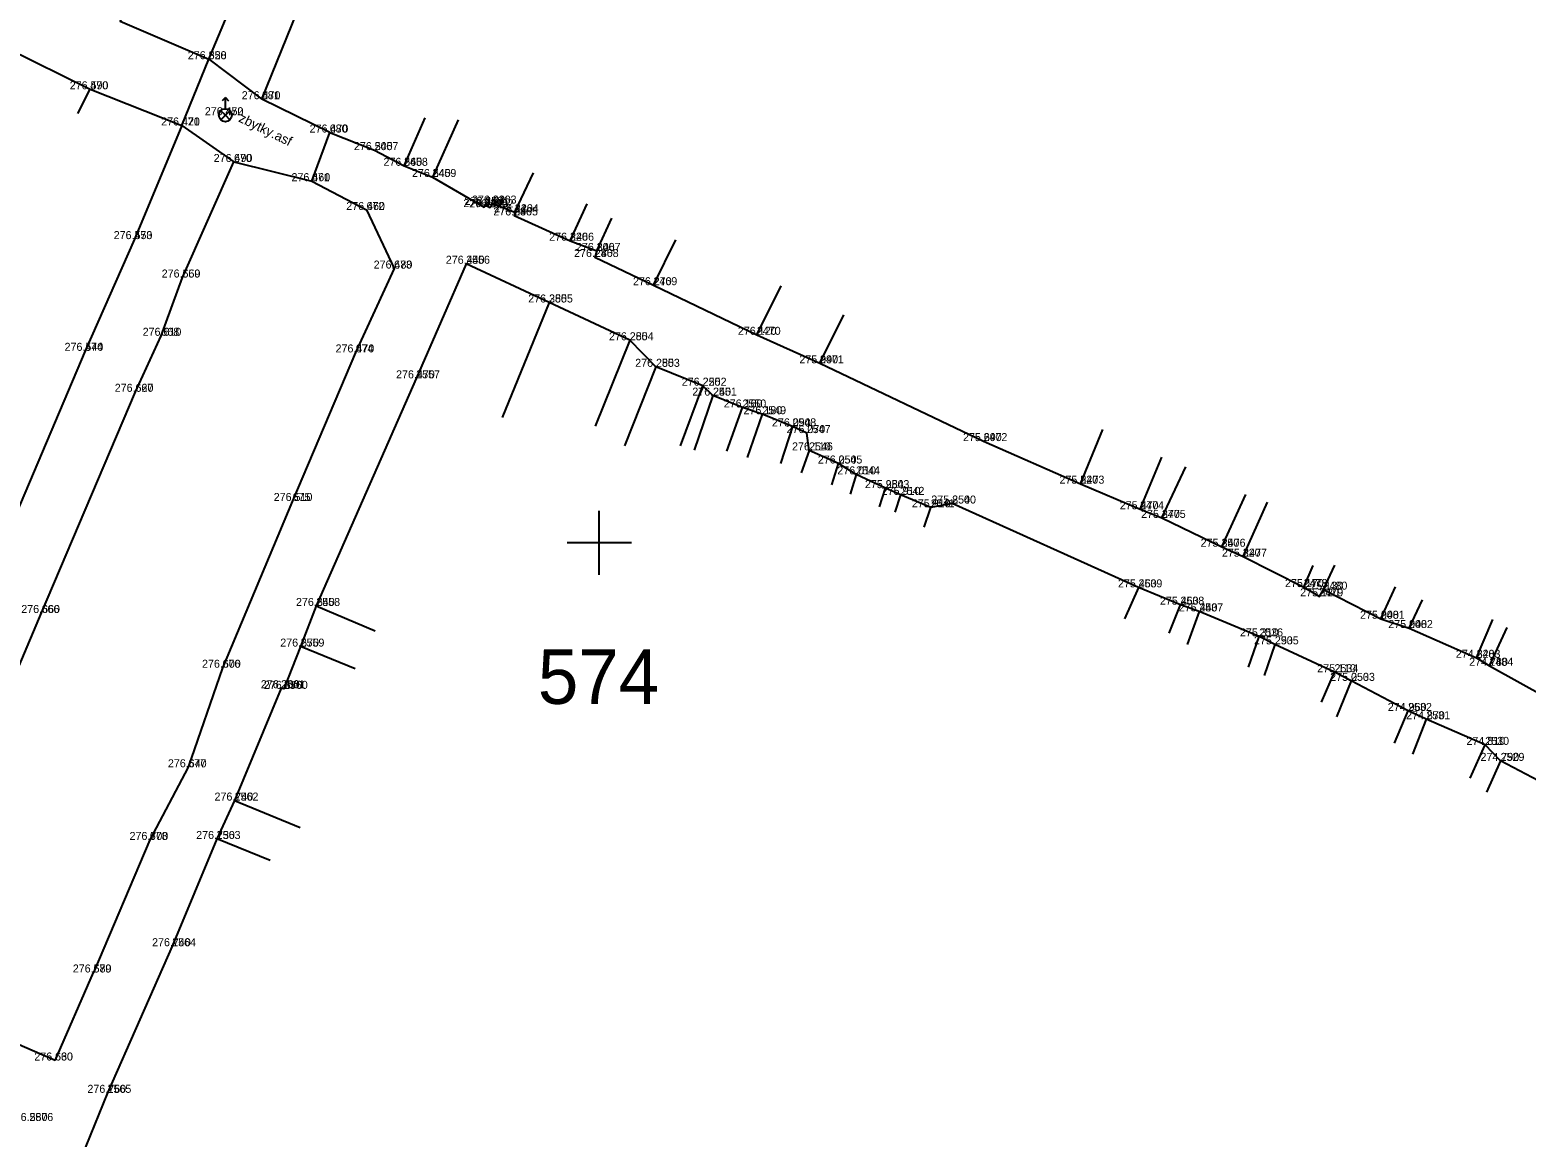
# Model space of a CAD drawing. Extents: x -776701 to -776081, y -974398 to -973771.
# Drawn here: x -776437.45 to -776390.72, y -974103.58 to -974068.99 of the extents above; entities that cross this region are included whole.
import ezdxf

# ---------------------------------------------------------------- set-up
doc = ezdxf.new("R2010")
doc.units = 0
for name, color, linetype in [('1 Body-bod', 7, 'Continuous'), ('10 Silnice-chodniky', 7, 'Continuous'), ('11 Rozhrani-nezpev zpev schody', 7, 'Continuous'), ('2 Body-cislo', 7, 'Continuous'), ('3 Body-vyska', 7, 'Continuous'), ('40 Popis-povrch', 7, 'Continuous'), ('58 Mobiliar', 7, 'Continuous'), ('7 Ploty', 7, 'Continuous'), ('Parcelní čísla', 7, 'Continuous'), ('Značky kultur', 7, 'Continuous')]:
    doc.layers.add(name, color=color, linetype=linetype)

msp = doc.modelspace()

# ---------------------------------------------------------------- linework, layer by layer
at = {"layer": '1 Body-bod'}
for p, q in [((-776431.87, -974069.91), (-776431.87, -974069.91)), ((-776435.57, -974070.85), (-776435.57, -974070.85)), ((-776430.21, -974071.16), (-776430.21, -974071.16)), ((-776431.35, -974071.66), (-776431.35, -974071.66)), ((-776432.71, -974071.98), (-776432.71, -974071.98)), ((-776428.09, -974072.2), (-776428.09, -974072.2)), ((-776426.69, -974072.75), (-776426.69, -974072.75)), ((-776431.08, -974073.12), (-776431.08, -974073.12)), ((-776425.77, -974073.24), (-776425.77, -974073.24)), ((-776428.65, -974073.72), (-776428.65, -974073.72)), ((-776424.88, -974073.59), (-776424.88, -974073.59)), ((-776426.94, -974074.62), (-776426.94, -974074.62)), ((-776423.27, -974074.53), (-776423.27, -974074.53)), ((-776423.24, -974074.46), (-776423.24, -974074.46)), ((-776423.09, -974074.54), (-776423.09, -974074.54)), ((-776423, -974074.42), (-776423, -974074.42)), ((-776422.31, -974074.69), (-776422.31, -974074.69)), ((-776422.33, -974074.79), (-776422.33, -974074.79)), ((-776434.19, -974075.53), (-776434.19, -974075.53)), ((-776420.58, -974075.58), (-776420.58, -974075.58)), ((-776419.81, -974076.09), (-776419.81, -974076.09)), ((-776419.75, -974075.9), (-776419.75, -974075.9)), ((-776426.08, -974076.45), (-776426.08, -974076.45)), ((-776423.83, -974076.3), (-776423.83, -974076.3)), ((-776432.69, -974076.73), (-776432.69, -974076.73)), ((-776417.98, -974076.97), (-776417.98, -974076.97)), ((-776421.24, -974077.51), (-776421.24, -974077.51)), ((-776433.35, -974078.55), (-776433.35, -974078.55)), ((-776418.72, -974078.69), (-776418.72, -974078.69)), ((-776414.75, -974078.52), (-776414.75, -974078.52)), ((-776435.73, -974079.02), (-776435.73, -974079.02)), ((-776427.28, -974079.07), (-776427.28, -974079.07)), ((-776417.9, -974079.52), (-776417.9, -974079.52)), ((-776412.78, -974079.41), (-776412.78, -974079.41)), ((-776434.16, -974080.3), (-776434.16, -974080.3)), ((-776425.39, -974079.88), (-776425.39, -974079.88)), ((-776416.44, -974080.11), (-776416.44, -974080.11)), ((-776416.12, -974080.42), (-776416.12, -974080.42)), ((-776415.2, -974080.79), (-776415.2, -974080.79)), ((-776414.58, -974081), (-776414.58, -974081)), ((-776413.64, -974081.38), (-776413.64, -974081.38)), ((-776413.19, -974081.59), (-776413.19, -974081.59)), ((-776413.12, -974082.13), (-776413.12, -974082.13)), ((-776407.67, -974081.84), (-776407.67, -974081.84)), ((-776412.2, -974082.54), (-776412.2, -974082.54)), ((-776411.65, -974082.88), (-776411.65, -974082.88)), ((-776410.73, -974083.31), (-776410.73, -974083.31)), ((-776410.26, -974083.52), (-776410.26, -974083.52)), ((-776404.64, -974083.17), (-776404.64, -974083.17)), ((-776429.25, -974083.71), (-776429.25, -974083.71)), ((-776409.32, -974083.91), (-776409.32, -974083.91)), ((-776408.65, -974083.79), (-776408.65, -974083.79)), ((-776402.78, -974083.97), (-776402.78, -974083.97)), ((-776402.1, -974084.24), (-776402.1, -974084.24)), ((-776400.23, -974085.14), (-776400.23, -974085.14)), ((-776399.56, -974085.45), (-776399.56, -974085.45)), ((-776402.83, -974086.41), (-776402.83, -974086.41)), ((-776397.67, -974086.4), (-776397.67, -974086.4)), ((-776397.18, -974086.69), (-776397.18, -974086.69)), ((-776397.05, -974086.48), (-776397.05, -974086.48)), ((-776437.09, -974087.21), (-776437.09, -974087.21)), ((-776428.51, -974086.99), (-776428.51, -974086.99)), ((-776401.52, -974086.95), (-776401.52, -974086.95)), ((-776400.93, -974087.16), (-776400.93, -974087.16)), ((-776395.26, -974087.39), (-776395.26, -974087.39)), ((-776394.38, -974087.68), (-776394.38, -974087.68)), ((-776429, -974088.26), (-776429, -974088.26)), ((-776399.06, -974087.94), (-776399.06, -974087.94)), ((-776398.57, -974088.19), (-776398.57, -974088.19)), ((-776392.27, -974088.61), (-776392.27, -974088.61)), ((-776431.44, -974088.92), (-776431.44, -974088.92)), ((-776396.71, -974089.06), (-776396.71, -974089.06)), ((-776391.87, -974088.86), (-776391.87, -974088.86)), ((-776429.61, -974089.56), (-776429.61, -974089.56)), ((-776429.52, -974089.58), (-776429.52, -974089.58)), ((-776396.19, -974089.33), (-776396.19, -974089.33)), ((-776394.41, -974090.27), (-776394.41, -974090.27)), ((-776393.84, -974090.53), (-776393.84, -974090.53)), ((-776392, -974091.33), (-776392, -974091.33)), ((-776391.52, -974091.83), (-776391.52, -974091.83)), ((-776432.51, -974092.03), (-776432.51, -974092.03)), ((-776431.06, -974093.07), (-776431.06, -974093.07)), ((-776433.71, -974094.3), (-776433.71, -974094.3)), ((-776431.62, -974094.27), (-776431.62, -974094.27)), ((-776433.01, -974097.62), (-776433.01, -974097.62)), ((-776435.47, -974098.44), (-776435.47, -974098.44)), ((-776436.67, -974101.19), (-776436.67, -974101.19)), ((-776435.03, -974102.2), (-776435.03, -974102.2))]:
    msp.add_line(p, q, dxfattribs=at)
at = {"layer": '10 Silnice-chodniky'}
for points in [[(-776432.71, -974071.98), (-776431.87, -974069.91), (-776430.21, -974071.16)], [(-776432.71, -974071.98), (-776431.08, -974073.12), (-776428.65, -974073.72), (-776428.09, -974072.2)]]:
    msp.add_lwpolyline(points, dxfattribs=at)
at = {"layer": '11 Rozhrani-nezpev zpev schody'}
for points in [[(-776438.19, -974069.55), (-776435.57, -974070.85)], [(-776425.77, -974073.24), (-776424.88, -974073.59)], [(-776428.65, -974073.72), (-776426.94, -974074.62), (-776426.08, -974076.45), (-776427.28, -974079.07)], [(-776417.98, -974076.97), (-776414.75, -974078.52)], [(-776417.9, -974079.52), (-776418.72, -974078.69)], [(-776412.78, -974079.41), (-776407.67, -974081.84), (-776404.64, -974083.17)], [(-776416.12, -974080.42), (-776416.44, -974080.11)], [(-776414.58, -974081), (-776415.2, -974080.79)], [(-776413.12, -974082.13), (-776413.19, -974081.59)], [(-776411.65, -974082.88), (-776412.2, -974082.54)], [(-776410.26, -974083.52), (-776410.73, -974083.31)], [(-776402.83, -974086.41), (-776408.65, -974083.79), (-776409.32, -974083.91)], [(-776402.78, -974083.97), (-776402.1, -974084.24)], [(-776400.23, -974085.14), (-776399.56, -974085.45)], [(-776428.51, -974086.99), (-776429, -974088.26)], [(-776400.93, -974087.16), (-776401.52, -974086.95)], [(-776395.26, -974087.39), (-776394.38, -974087.68)], [(-776398.57, -974088.19), (-776399.06, -974087.94)], [(-776392.27, -974088.61), (-776391.87, -974088.86)], [(-776396.19, -974089.33), (-776396.71, -974089.06)], [(-776393.84, -974090.53), (-776394.41, -974090.27)], [(-776391.52, -974091.83), (-776392, -974091.33)], [(-776431.06, -974093.07), (-776431.62, -974094.27)]]:
    msp.add_lwpolyline(points, dxfattribs=at)
at = {"layer": '58 Mobiliar'}
for p, q in [((-776431.35, -974071.11), (-776431.45, -974071.21)), ((-776431.35, -974071.459), (-776431.35, -974071.11)), ((-776431.35, -974071.11), (-776431.25, -974071.21)), ((-776431.35, -974071.66), (-776431.493, -974071.518)), ((-776431.35, -974071.66), (-776431.493, -974071.802)), ((-776431.35, -974071.66), (-776431.208, -974071.518)), ((-776431.35, -974071.66), (-776431.35, -974071.66)), ((-776431.35, -974071.66), (-776431.208, -974071.802))]:
    msp.add_line(p, q, dxfattribs=at)
msp.add_circle((-776431.35, -974071.66), 0.202, dxfattribs=at)
at = {"layer": '7 Ploty'}
for p, q in [((-776422.31, -974074.69), (-776421.721, -974073.459)), ((-776420.58, -974075.58), (-776420.052, -974074.428)), ((-776419.75, -974075.9), (-776419.276, -974074.873)), ((-776417.98, -974076.97), (-776417.275, -974075.553)), ((-776414.75, -974078.52), (-776413.99, -974076.989)), ((-776421.24, -974077.51), (-776422.701, -974081.098)), ((-776412.78, -974079.41), (-776412.037, -974077.897)), ((-776418.72, -974078.69), (-776419.803, -974081.37)), ((-776413.64, -974081.38), (-776414.011, -974082.538)), ((-776404.64, -974083.17), (-776403.942, -974081.479)), ((-776402.78, -974083.97), (-776402.096, -974082.341)), ((-776402.1, -974084.24), (-776401.355, -974082.644)), ((-776400.23, -974085.14), (-776399.479, -974083.507)), ((-776399.56, -974085.45), (-776398.798, -974083.749)), ((-776397.67, -974086.4), (-776397.376, -974085.729)), ((-776397.05, -974086.48), (-776396.693, -974085.712)), ((-776395.26, -974087.39), (-776394.8, -974086.395)), ((-776394.38, -974087.68), (-776393.961, -974086.802)), ((-776392.27, -974088.61), (-776391.761, -974087.412)), ((-776391.87, -974088.86), (-776391.32, -974087.663))]:
    msp.add_line(p, q, dxfattribs=at)
for points in [[(-776434.064, -974067.386), (-776434.63, -974068.72), (-776431.87, -974069.91), (-776429.07, -974063.23), (-776425.96, -974055.99), (-776423.44, -974050.16), (-776419.96, -974041.94), (-776416.42, -974033.77), (-776418.73, -974032.17), (-776419.374, -974033.733)], [(-776428.09, -974072.2), (-776430.21, -974071.16), (-776428.8, -974067.68), (-776427.94, -974065.4), (-776427.28, -974063.93), (-776424.21, -974056.81), (-776421.9, -974051.26), (-776418.44, -974043.46), (-776414.98, -974035.26)], [(-776435.955, -974071.605), (-776435.57, -974070.85), (-776432.71, -974071.98), (-776434.19, -974075.53), (-776435.73, -974079.02), (-776438.7, -974086), (-776442.73, -974095.55), (-776443.45, -974095.25)], [(-776428.09, -974072.2), (-776426.69, -974072.75), (-776425.77, -974073.24), (-776425.111, -974071.746)], [(-776424.082, -974071.807), (-776424.88, -974073.59), (-776423.27, -974074.53), (-776423.24, -974074.46), (-776423.09, -974074.54), (-776423, -974074.42), (-776422.31, -974074.69), (-776422.33, -974074.79), (-776420.58, -974075.58), (-776419.75, -974075.9), (-776419.81, -974076.09), (-776417.98, -974076.97)], [(-776436.67, -974101.19), (-776442.04, -974098.86), (-776441.45, -974097.48), (-776441.68, -974097.37), (-776441.38, -974096.63), (-776441.12, -974096.74), (-776437.09, -974087.21), (-776434.16, -974080.3), (-776433.35, -974078.55), (-776432.69, -974076.73), (-776431.08, -974073.12)], [(-776418.72, -974078.69), (-776421.24, -974077.51), (-776423.83, -974076.3), (-776425.39, -974079.88), (-776428.51, -974086.99), (-776426.666, -974087.767)], [(-776414.75, -974078.52), (-776412.78, -974079.41)], [(-776427.28, -974079.07), (-776429.25, -974083.71), (-776431.44, -974088.92), (-776432.51, -974092.03), (-776433.71, -974094.3), (-776435.47, -974098.44)], [(-776417.13, -974081.993), (-776416.44, -974080.11), (-776417.9, -974079.52), (-776418.887, -974081.993)], [(-776415.684, -974082.159), (-776415.2, -974080.79), (-776416.12, -974080.42), (-776416.71, -974082.123)], [(-776413.19, -974081.59), (-776413.64, -974081.38), (-776414.58, -974081), (-776415.049, -974082.352)], [(-776412.408, -974083.203), (-776412.2, -974082.54), (-776413.12, -974082.13), (-776413.366, -974082.83)], [(-776410.924, -974083.893), (-776410.73, -974083.31), (-776411.65, -974082.88), (-776411.834, -974083.493)], [(-776409.527, -974084.524), (-776409.32, -974083.91), (-776410.26, -974083.52), (-776410.445, -974084.063)], [(-776404.64, -974083.17), (-776402.78, -974083.97)], [(-776402.1, -974084.24), (-776400.23, -974085.14)], [(-776399.56, -974085.45), (-776397.67, -974086.4), (-776397.18, -974086.69), (-776397.05, -974086.48), (-776395.26, -974087.39)], [(-776401.873, -974087.838), (-776401.52, -974086.95), (-776402.83, -974086.41), (-776403.263, -974087.389)], [(-776399.395, -974088.898), (-776399.06, -974087.94), (-776400.93, -974087.16), (-776401.305, -974088.199)], [(-776394.38, -974087.68), (-776392.27, -974088.61)], [(-776427.297, -974088.957), (-776429, -974088.26), (-776429.52, -974089.58), (-776429.61, -974089.56), (-776431.06, -974093.07), (-776429.011, -974093.916)], [(-776397.119, -974089.992), (-776396.71, -974089.06), (-776398.57, -974088.19), (-776398.904, -974089.164)], [(-776391.87, -974088.86), (-776390.04, -974089.87)], [(-776394.831, -974091.272), (-776394.41, -974090.27), (-776396.19, -974089.33), (-776396.642, -974090.454)], [(-776392.471, -974092.37), (-776392, -974091.33), (-776393.84, -974090.53), (-776394.272, -974091.624)], [(-776390.153, -974093.654), (-776389.74, -974092.77), (-776391.52, -974091.83), (-776391.964, -974092.805)], [(-776429.948, -974094.946), (-776431.62, -974094.27), (-776433.01, -974097.62), (-776435.03, -974102.2), (-776436.93, -974106.86), (-776438.69, -974111.11), (-776440.9, -974116.22), (-776441.31, -974116.05), (-776442.26, -974118.23), (-776442.32, -974118.39), (-776439.31, -974119.75), (-776436.7, -974120.98), (-776436.365, -974120.318)], [(-776436.67, -974101.19), (-776435.47, -974098.44)]]:
    msp.add_lwpolyline(points, dxfattribs=at)
at = {"layer": 'Značky kultur'}
for p, q in [((-776419.67, -974086.02), (-776419.67, -974084.02)), ((-776418.669, -974085.021), (-776420.671, -974085.021))]:
    msp.add_line(p, q, dxfattribs=at)

# ---------------------------------------------------------------- texts
at = {"layer": '2 Body-cislo'}
for s, p in [('528', (-776431.87, -974069.91)), ('470', (-776435.57, -974070.85)), ('681', (-776430.21, -974071.16)), ('472', (-776431.35, -974071.66)), ('471', (-776432.71, -974071.98)), ('680', (-776428.09, -974072.2)), ('670', (-776431.08, -974073.12)), ('2457', (-776426.69, -974072.75)), ('2458', (-776425.77, -974073.24)), ('671', (-776428.65, -974073.72)), ('2459', (-776424.88, -974073.59)), ('2461', (-776423.24, -974074.46)), ('2463', (-776423, -974074.42)), ('672', (-776426.94, -974074.62)), ('2460', (-776423.27, -974074.53)), ('2462', (-776423.09, -974074.54)), ('2465', (-776422.33, -974074.79)), ('2464', (-776422.31, -974074.69)), ('473', (-776434.19, -974075.53)), ('2466', (-776420.58, -974075.58)), ('2467', (-776419.75, -974075.9)), ('2556', (-776423.83, -974076.3)), ('2468', (-776419.81, -974076.09)), ('669', (-776432.69, -974076.73)), ('673', (-776426.08, -974076.45)), ('2469', (-776417.98, -974076.97)), ('2555', (-776421.24, -974077.51)), ('668', (-776433.35, -974078.55)), ('2554', (-776418.72, -974078.69)), ('2470', (-776414.75, -974078.52)), ('474', (-776435.73, -974079.02)), ('674', (-776427.28, -974079.07)), ('2553', (-776417.9, -974079.52)), ('2471', (-776412.78, -974079.41)), ('2557', (-776425.39, -974079.88)), ('2552', (-776416.44, -974080.11)), ('667', (-776434.16, -974080.3)), ('2551', (-776416.12, -974080.42)), ('2550', (-776415.2, -974080.79)), ('2549', (-776414.58, -974081)), ('2548', (-776413.64, -974081.38)), ('2547', (-776413.19, -974081.59)), ('2472', (-776407.67, -974081.84)), ('2546', (-776413.12, -974082.13)), ('2545', (-776412.2, -974082.54)), ('2544', (-776411.65, -974082.88)), ('2543', (-776410.73, -974083.31)), ('2473', (-776404.64, -974083.17)), ('675', (-776429.25, -974083.71)), ('2542', (-776410.26, -974083.52)), ('2540', (-776408.65, -974083.79)), ('2541', (-776409.32, -974083.91)), ('2474', (-776402.78, -974083.97)), ('2475', (-776402.1, -974084.24)), ('2476', (-776400.23, -974085.14)), ('2477', (-776399.56, -974085.45)), ('2539', (-776402.83, -974086.41)), ('2478', (-776397.67, -974086.4)), ('2480', (-776397.05, -974086.48)), ('2558', (-776428.51, -974086.99)), ('2538', (-776401.52, -974086.95)), ('2479', (-776397.18, -974086.69)), ('666', (-776437.09, -974087.21)), ('2537', (-776400.93, -974087.16)), ('2481', (-776395.26, -974087.39)), ('2536', (-776399.06, -974087.94)), ('2482', (-776394.38, -974087.68)), ('2559', (-776429, -974088.26)), ('2535', (-776398.57, -974088.19)), ('676', (-776431.44, -974088.92)), ('2483', (-776392.27, -974088.61)), ('2484', (-776391.87, -974088.86)), ('2534', (-776396.71, -974089.06)), ('2533', (-776396.19, -974089.33)), ('2561', (-776429.61, -974089.56)), ('2560', (-776429.52, -974089.58)), ('2532', (-776394.41, -974090.27)), ('2531', (-776393.84, -974090.53)), ('2530', (-776392, -974091.33)), ('677', (-776432.51, -974092.03)), ('2529', (-776391.52, -974091.83)), ('2562', (-776431.06, -974093.07)), ('678', (-776433.71, -974094.3)), ('2563', (-776431.62, -974094.27)), ('2564', (-776433.01, -974097.62)), ('679', (-776435.47, -974098.44)), ('660', (-776436.67, -974101.19)), ('2565', (-776435.03, -974102.2)), ('2576', (-776437.47, -974103.08))]:
    msp.add_text(s, height=0.25, dxfattribs=at).set_placement(p)
at = {"layer": '3 Body-vyska'}
for s, p in [('276.350', (-776432.523, -974069.91)), ('276.590', (-776436.211, -974070.85)), ('276.470', (-776430.838, -974071.16)), ('276.450', (-776431.991, -974071.66)), ('276.420', (-776433.355, -974071.98)), ('276.470', (-776428.718, -974072.2)), ('276.490', (-776431.714, -974073.12)), ('276.500', (-776427.335, -974072.75)), ('276.560', (-776426.411, -974073.24)), ('276.460', (-776429.284, -974073.72)), ('276.540', (-776425.521, -974073.59)), ('276.450', (-776423.881, -974074.46)), ('276.430', (-776423.647, -974074.42)), ('276.460', (-776427.574, -974074.62)), ('276.420', (-776423.915, -974074.53)), ('276.420', (-776423.735, -974074.54)), ('276.380', (-776422.981, -974074.79)), ('276.420', (-776422.955, -974074.69)), ('276.550', (-776434.838, -974075.53)), ('276.320', (-776421.237, -974075.58)), ('276.300', (-776420.401, -974075.9)), ('276.440', (-776424.464, -974076.3)), ('276.280', (-776420.459, -974076.09)), ('276.550', (-776433.338, -974076.73)), ('276.480', (-776426.718, -974076.45)), ('276.270', (-776418.619, -974076.97)), ('276.380', (-776421.891, -974077.51)), ('276.610', (-776433.933, -974078.55)), ('276.280', (-776419.369, -974078.69)), ('276.120', (-776415.343, -974078.52)), ('276.540', (-776436.371, -974079.02)), ('276.470', (-776427.908, -974079.07)), ('276.280', (-776418.549, -974079.52)), ('275.990', (-776413.421, -974079.41)), ('276.470', (-776426.018, -974079.88)), ('276.220', (-776417.095, -974080.11)), ('276.620', (-776434.805, -974080.3)), ('276.240', (-776416.765, -974080.42)), ('276.160', (-776415.783, -974080.79)), ('276.180', (-776415.167, -974081)), ('276.090', (-776414.278, -974081.38)), ('276.070', (-776413.822, -974081.59)), ('275.690', (-776408.311, -974081.84)), ('276.110', (-776413.651, -974082.13)), ('276.050', (-776412.845, -974082.54)), ('276.010', (-776412.237, -974082.88)), ('275.980', (-776411.375, -974083.31)), ('275.520', (-776405.298, -974083.17)), ('276.510', (-776429.839, -974083.71)), ('275.910', (-776410.849, -974083.52)), ('275.850', (-776409.302, -974083.79)), ('275.910', (-776409.909, -974083.91)), ('275.470', (-776403.415, -974083.97)), ('275.370', (-776402.748, -974084.24)), ('275.350', (-776400.89, -974085.14)), ('275.320', (-776400.224, -974085.45)), ('275.460', (-776403.471, -974086.41)), ('275.170', (-776398.254, -974086.4)), ('275.130', (-776397.652, -974086.48)), ('276.640', (-776429.144, -974086.99)), ('275.460', (-776402.161, -974086.95)), ('275.120', (-776397.78, -974086.69)), ('276.660', (-776437.724, -974087.21)), ('275.440', (-776401.571, -974087.16)), ('275.000', (-776395.909, -974087.39)), ('275.310', (-776399.662, -974087.94)), ('275.000', (-776395.029, -974087.68)), ('276.570', (-776429.635, -974088.26)), ('275.290', (-776399.222, -974088.19)), ('276.600', (-776432.078, -974088.92)), ('274.820', (-776392.919, -974088.61)), ('274.780', (-776392.502, -974088.86)), ('275.110', (-776397.248, -974089.06)), ('275.050', (-776396.842, -974089.33)), ('276.700', (-776430.242, -974089.56)), ('276.670', (-776430.148, -974089.58)), ('274.960', (-776395.044, -974090.27)), ('274.870', (-776394.472, -974090.53)), ('274.810', (-776392.587, -974091.33)), ('276.640', (-776433.144, -974092.03)), ('274.790', (-776392.148, -974091.83)), ('276.740', (-776431.688, -974093.07)), ('276.700', (-776434.342, -974094.3)), ('276.730', (-776432.261, -974094.27)), ('276.740', (-776433.638, -974097.62)), ('276.580', (-776436.115, -974098.44)), ('276.630', (-776437.317, -974101.19)), ('276.760', (-776435.658, -974102.2)), ('276.580', (-776438.115, -974103.08))]:
    msp.add_text(s, height=0.25, dxfattribs=at).set_placement(p)
at = {"layer": '40 Popis-povrch'}
msp.add_text('zbytky.asf', height=0.3, rotation=333.869, dxfattribs=at).set_placement((-776430.96, -974071.847))
at = {"layer": 'Parcelní čísla'}
msp.add_text('574', height=1.7, dxfattribs=at).set_placement((-776421.59, -974090.05))

doc.saveas('drawing.dxf')
